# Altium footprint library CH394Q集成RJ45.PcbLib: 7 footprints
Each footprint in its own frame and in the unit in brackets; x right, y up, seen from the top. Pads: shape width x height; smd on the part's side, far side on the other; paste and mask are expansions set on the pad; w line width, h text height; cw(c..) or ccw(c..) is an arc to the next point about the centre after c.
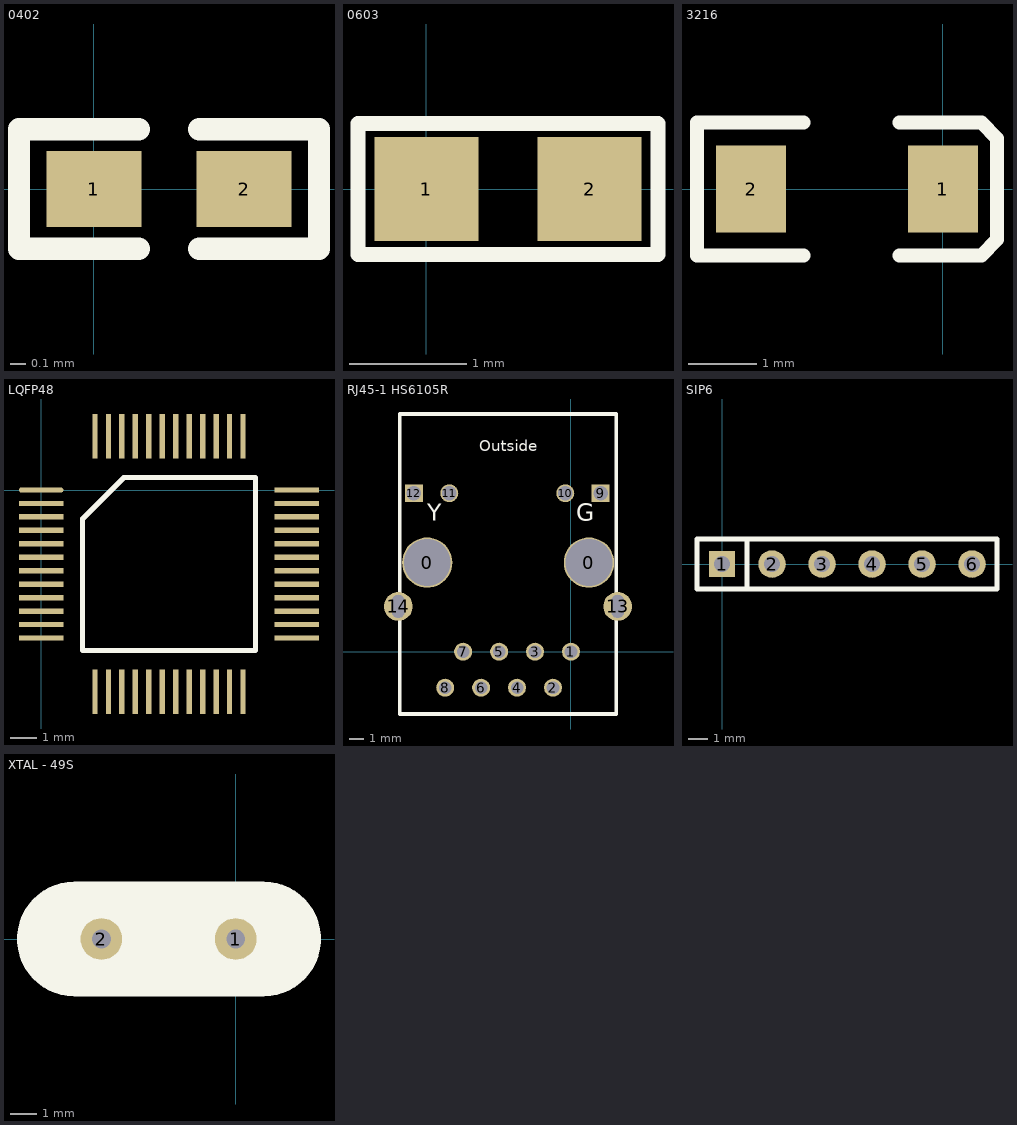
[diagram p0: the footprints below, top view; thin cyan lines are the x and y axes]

## 0402 [mil]
height 43.31
pads (2):
  rect 25x20 smd: 1(0,0) 2(39.37,0)
Top Overlay:
  lines w5.91: 11.81,-15.75 -19.68,-15.75 -19.68,15.75 11.81,15.75 ; 27.56,-15.75 59.06,-15.75 59.06,15.75 27.56,15.75

## 0603 [mil]
height 43.31
pads (2):
  rect 35x35 smd: 1(0,0) 2(55,0)
Top Overlay:
  lines w5: -23,-22 78,-22 78,22 -23,22 -23,-22

## 3216 [mil]
height 43.31
pads (2):
  rect 40x50 smd: 1(0,0) 2(-110,0)
Top Overlay:
  lines w8: -80,-38 -141,-38 -141,38 -80,38 ; -25,-38 22,-38 31,-29 31,29 22,38 -25,38

## LQFP48 [mm]
height 1.1
pads (48):
  oval 1.651x0.2 smd: 1(0,0)
  rect 1.651x0.2 smd: 2(0,-0.5) 3(0,-1) 4(0,-1.5) 5(0,-2) 6(0,-2.5) 7(0,-3) 8(0,-3.5) 9(0,-4) 10(0,-4.5) 11(0,-5) 12(0,-5.5) 25(9.5,-5.5) 26(9.5,-5) 27(9.5,-4.5) 28(9.5,-4) 29(9.5,-3.5) 30(9.5,-3) 31(9.5,-2.5) 32(9.5,-2) 33(9.5,-1.5) 34(9.5,-1) 35(9.5,-0.5) 36(9.5,0)
  rect 0.2x1.651 smd: 13(2,-7.5) 14(2.5,-7.5) 15(3,-7.5) 16(3.5,-7.5) 17(4,-7.5) 18(4.5,-7.5) 19(5,-7.5) 20(5.5,-7.5) 21(6,-7.5) 22(6.5,-7.5) 23(7,-7.5) 24(7.5,-7.5) 37(7.5,2) 38(7,2) 39(6.5,2) 40(6,2) 41(5.5,2) 42(5,2) 43(4.5,2) 44(4,2) 45(3.5,2) 46(3,2) 47(2.5,2) 48(2,2)
Top Overlay:
  lines w0.2: 1.535,-5.965 1.535,-1.07 3.07,0.465 7.965,0.465 7.965,-5.965 1.535,-5.965

## RJ45-1 HS6105R [mil]
height 537.8
pads (16):
  round 140 hole 130: 0(-400,248.03) 0(50,248.03)
  round 50 hole 35: 1(0,0) 2(-50,-100) 3(-100,0) 4(-150,-100) 5(-200,0) 6(-250,-100) 7(-300,0) 8(-350,-100)
  rect 50x50 hole 40: 9(82.68,440.94) 12(-437.01,440.94)
  round 50 hole 40: 10(-15.75,440.94) 11(-338.58,440.94)
  round 80 hole 35.43 slot 64.02 at 90 deg: 13(129.92,125.98) 14(-480.31,125.98)
Top Overlay:
  lines w10: -476.38,-173.23 125.98,-173.23 125.98,661.42 -476.38,661.42 -476.38,-173.23
  text "Outside" at -255,558.03 h30
  text "G" at 15,365 h47.24
  text "Y" at -400,365 h47.24

## SIP6 [mil]
height 43.31
pads (6):
  rect 51.06x51.06 hole 32: 1(0,0)
  round 55 hole 32: 2(100,0) 3(200,0) 4(300,0) 5(400,0) 6(500,0)
Top Overlay:
  lines w10: 50,-50 50,50 ; -50,-50 -50,50 550,50 550,-50 -50,-50

## XTAL - 49S [mil]
pads (2):
  round 62 hole 28: 1(0,0) 2(-200,0)
Top Overlay:
  region: -264.02,74 -280.02,74 -280.02,-73 -264.02,-73
  region: -253.02,79 -273.02,79 -273.02,-78 -253.02,-78
  region: -240.02,80.01 -259.02,80.01 -259.02,-82.67 -240.02,-82.67
  region: 41.34,82.68 -240,82.68 -240,-82.67 41.34,-82.67
  region: 58,81 41.34,81 41.34,-82.68 58,-82.68
  region: 69.98,81 57.98,81 57.98,-78 69.98,-78
  region: 78.98,75 68.98,75 68.98,-75 78.98,-75
  region: 87.98,71 76.98,71 76.98,-70 87.98,-70
  lines w6: -240,-82.68 cw(c-240,0) -240,82.68 41.34,82.68 cw(c41.34,0) 41.34,-82.68 -240,-82.68
  lines w10: -317,-24 -317,23 -311,29 -311,-37 -308,-40 -308,43 -302,49 -302,-46 -298,-50 -298,54 -294,58 -294,-55 -289,-60 -289,57 -290,58 -290,59 -283,66 -283,-61 ; 88,-60 90,-58 90,63 91,63 97,57 97,-54 96,-55 100,-51 100,49 111,38 106,33 106,-43 112,-37 112,-33 112,30 118,24 118,-25 ; -283,-61 -280,-64 -283,-61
